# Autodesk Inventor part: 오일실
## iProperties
IsCustomPart: 0
Company: 한국ATC센터
Created: 2014-08
Part Number: 오일실
Material: 고무
Description: 오일-실
Document SubType Name: Modeling
Standard: KS B 2804
Designer: KYOUNG IL JANG
Standards Organization: KS
Language: ko-KR
Size Designation: S - 17 30 8
Categories: <MemberInstance><Categories><Category DisplayName="샤프트 부품" InternalName="7f7aeb1f-a693-4053-b835-cee3144e0d98" Mnemonic="SHFT"><Category DisplayName="실링" Intern
Density: 0.93 g/cm^3
Author: KYOUNG IL JANG
